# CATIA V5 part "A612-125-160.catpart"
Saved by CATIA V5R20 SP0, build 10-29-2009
Part number: A612-125-160
Source: Unknown
Property "A": "30.000"
Property "ARTICLENO": "A612-125-160"
Property "B": "50.000"
Property "BOMINFO": "A612-125-160"
Property "CODE": "A612-125-160"
Property "D": "22.000"
Property "FORM": "A"
Property "L": "160.000"
Property "L1": "45.000"
Property "L2": "70.000"
Property "L3": "0.000"
Property "LINA": "A612-125-160"
Property "NB": "A612-125-160"
Property "NBSYN": "$CODE."
Property "NN": "A612"
Property "NT": "CDI 3357 E-Type Wear Plates, steel and self-lubricating"
Property "SUPPLIER": "CF"
Property "T": "30.000"
Property "W": "125.000"
Bounding box of the stored display mesh (mm): x 0 to 30, y 0 to 160, z 0 to 125
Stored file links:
  C:\Users\Utente\Desktop\3D files A612\A612-125-160.catpart

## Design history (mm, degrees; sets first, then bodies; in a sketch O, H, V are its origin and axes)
Body1 "Geometry.1" (main body)
  Solid1 "A612-125-160.catpart": solid without history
